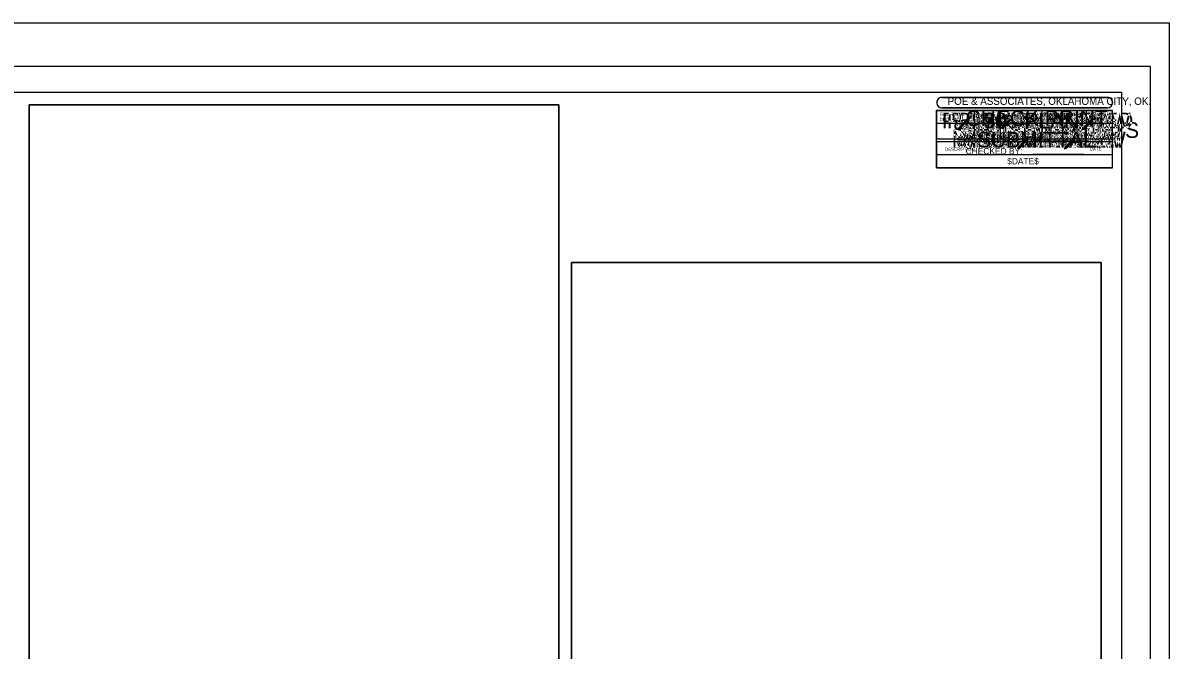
# Model space of a CAD drawing. Extents: x -1.6 to 34.4, y -1.2 to 22.8.
# Drawn here: x 12.44 to 34.36, y 10.82 to 22.82 of the extents above; entities that cross this region are included whole.
import ezdxf

# ---------------------------------------------------------------- set-up
doc = ezdxf.new("R2010")
doc.units = 0
for name, color, linetype in [('Default', 7, 'Continuous'), ('PR_OLE_MS_Excel', 7, 'Continuous'), ('SHT_Date_Stamp', 7, 'Continuous'), ('SHT_Plot_Shape_Full', 7, 'Continuous'), ('SHT_Plot_Shape_Half', 7, 'Continuous'), ('SHT_Sheet_Border', 7, 'Continuous'), ('SHT_Stamp_30_Submit', 7, 'Continuous'), ('SHT_Stamp_70_Submit', 7, 'Continuous'), ('SHT_Stamp_90_Submit', 7, 'Continuous'), ('SHT_Stamp_Check_Print', 7, 'Continuous'), ('SHT_Stamp_Est_Inf', 7, 'Continuous'), ('SHT_Stamp_FFR', 7, 'Continuous'), ('SHT_Stamp_Info_Material', 7, 'Continuous'), ('SHT_Stamp_No_Const', 7, 'Continuous'), ('SHT_Stamp_No_Design', 7, 'Continuous'), ('SHT_Stamp_Plan_Hand', 7, 'Continuous'), ('SHT_Stamp_Pre_Plan', 7, 'Continuous'), ('SHT_Stamp_Prop_RW', 7, 'Continuous'), ('SHT_Stamp_Ret_Sub', 7, 'Continuous'), ('SHT_Stamp_Rev_Block', 7, 'Continuous'), ('SHT_Stamp_Rev_Prop_RW', 7, 'Continuous'), ('SHT_Stamp_Rev_Sheet', 7, 'Continuous'), ('SHT_Stamp_RW_Utilities_Meeting', 7, 'Continuous'), ('SHT_Stamp_RW_Utilities_Review', 7, 'Continuous'), ('SHT_Stamp_Send_Comments', 7, 'Continuous')]:
    doc.layers.add(name, color=color, linetype=linetype)

msp = doc.modelspace()

# ---------------------------------------------------------------- linework, layer by layer
at = {"layer": 'Default'}
for points in [[(12.56, 2.371), (22.69, 2.371), (22.69, 21.26), (12.56, 21.26)], [(22.93, 2.371), (33.061, 2.371), (33.061, 18.239), (22.93, 18.239)]]:
    msp.add_lwpolyline(points, close=True, dxfattribs=at)
at = {"layer": 'PR_OLE_MS_Excel'}
for points in [[(12.56, 21.26), (22.69, 21.26), (22.69, 2.371), (12.56, 2.371)], [(22.93, 18.239), (33.061, 18.239), (33.061, 2.371), (22.93, 2.371)]]:
    msp.add_lwpolyline(points, close=True, dxfattribs=at)
at = {"layer": 'SHT_Plot_Shape_Full'}
msp.add_lwpolyline([(-1.638, 22.825), (34.362, 22.825), (34.362, -1.175), (-1.638, -1.175)], close=True, dxfattribs=at)
at = {"layer": 'SHT_Plot_Shape_Half'}
msp.add_lwpolyline([(0, 22), (34, 22), (34, 0), (0, 0)], close=True, dxfattribs=at)
at = {"layer": 'SHT_Sheet_Border'}
msp.add_lwpolyline([(33.45, 0.5), (1.95, 0.5), (1.95, 21.5), (33.45, 21.5)], close=True, dxfattribs=at)
at = {"layer": 'SHT_Stamp_30_Submit'}
for p, q in [((30.017, 21.4), (33.183, 21.4)), ((29.917, 21.15), (33.283, 21.15)), ((29.917, 20.051), (29.917, 21.15)), ((30.017, 21.2), (33.183, 21.2)), ((33.283, 20.051), (33.283, 21.15)), ((31.161, 20.812), (31.316, 20.984)), ((31.178, 20.812), (31.334, 20.984)), ((31.183, 20.812), (31.339, 20.984)), ((31.191, 20.812), (31.347, 20.984)), ((31.316, 20.984), (31.347, 20.984)), ((31.161, 20.812), (31.191, 20.812)), ((29.917, 20.051), (33.283, 20.051))]:
    msp.add_line(p, q, dxfattribs=at)
for centre, start, end in [((30.018, 21.3), 89.9952, 270), ((33.184, 21.3), 270, 90.0048)]:
    msp.add_arc(centre, 0.1, start, end, dxfattribs=at)
at = {"layer": 'SHT_Stamp_70_Submit'}
for p, q in [((30.017, 21.4), (33.183, 21.4)), ((29.917, 21.15), (33.283, 21.15)), ((29.917, 20.051), (29.917, 21.15)), ((30.017, 21.2), (33.183, 21.2)), ((33.283, 20.051), (33.283, 21.15)), ((31.161, 20.812), (31.316, 20.984)), ((31.178, 20.812), (31.334, 20.984)), ((31.183, 20.812), (31.339, 20.984)), ((31.191, 20.812), (31.347, 20.984)), ((31.316, 20.984), (31.347, 20.984)), ((31.161, 20.812), (31.191, 20.812)), ((29.917, 20.051), (33.283, 20.051))]:
    msp.add_line(p, q, dxfattribs=at)
for centre, start, end in [((30.018, 21.3), 89.9952, 270), ((33.184, 21.3), 270, 90.0048)]:
    msp.add_arc(centre, 0.1, start, end, dxfattribs=at)
at = {"layer": 'SHT_Stamp_90_Submit'}
for p, q in [((30.017, 21.4), (33.183, 21.4)), ((29.917, 21.15), (33.283, 21.15)), ((29.917, 20.051), (29.917, 21.15)), ((30.017, 21.2), (33.183, 21.2)), ((33.283, 20.051), (33.283, 21.15)), ((31.161, 20.812), (31.316, 20.984)), ((31.178, 20.812), (31.334, 20.984)), ((31.183, 20.812), (31.339, 20.984)), ((31.191, 20.812), (31.347, 20.984)), ((31.316, 20.984), (31.347, 20.984)), ((31.161, 20.812), (31.191, 20.812)), ((29.917, 20.051), (33.283, 20.051))]:
    msp.add_line(p, q, dxfattribs=at)
for centre, start, end in [((30.018, 21.3), 89.9952, 270), ((33.184, 21.3), 270, 90.0048)]:
    msp.add_arc(centre, 0.1, start, end, dxfattribs=at)
at = {"layer": 'SHT_Stamp_Check_Print'}
for p, q in [((30.017, 21.4), (33.183, 21.4)), ((29.917, 21.15), (33.283, 21.15)), ((29.917, 20.051), (29.917, 21.15)), ((30.017, 21.2), (33.183, 21.2)), ((33.283, 20.051), (33.283, 21.15)), ((31.759, 20.569), (32.73, 20.569)), ((31.759, 20.313), (32.73, 20.313)), ((29.917, 20.051), (33.283, 20.051))]:
    msp.add_line(p, q, dxfattribs=at)
for centre, start, end in [((30.018, 21.3), 89.9952, 270), ((33.184, 21.3), 270, 90.0048)]:
    msp.add_arc(centre, 0.1, start, end, dxfattribs=at)
at = {"layer": 'SHT_Stamp_Est_Inf'}
for p, q in [((30.017, 21.4), (33.183, 21.4)), ((29.917, 21.15), (33.283, 21.15)), ((29.917, 20.051), (29.917, 21.15)), ((30.017, 21.2), (33.183, 21.2)), ((33.283, 20.051), (33.283, 21.15)), ((29.917, 20.051), (33.283, 20.051))]:
    msp.add_line(p, q, dxfattribs=at)
for centre, start, end in [((30.018, 21.3), 89.9952, 270), ((33.184, 21.3), 270, 90.0048)]:
    msp.add_arc(centre, 0.1, start, end, dxfattribs=at)
at = {"layer": 'SHT_Stamp_FFR'}
for p, q in [((30.017, 21.4), (33.183, 21.4)), ((29.917, 21.15), (33.283, 21.15)), ((29.917, 20.051), (29.917, 21.15)), ((30.017, 21.2), (33.183, 21.2)), ((33.283, 20.051), (33.283, 21.15)), ((29.917, 20.051), (33.283, 20.051))]:
    msp.add_line(p, q, dxfattribs=at)
for centre, start, end in [((30.018, 21.3), 89.9952, 270), ((33.184, 21.3), 270, 90.0048)]:
    msp.add_arc(centre, 0.1, start, end, dxfattribs=at)
at = {"layer": 'SHT_Stamp_Info_Material'}
for p, q in [((30.017, 21.4), (33.183, 21.4)), ((29.917, 21.15), (33.283, 21.15)), ((29.917, 20.051), (29.917, 21.15)), ((30.017, 21.2), (33.183, 21.2)), ((33.283, 20.051), (33.283, 21.15)), ((29.917, 20.051), (33.283, 20.051))]:
    msp.add_line(p, q, dxfattribs=at)
for centre, start, end in [((30.018, 21.3), 89.9952, 270), ((33.184, 21.3), 270, 90.0048)]:
    msp.add_arc(centre, 0.1, start, end, dxfattribs=at)
at = {"layer": 'SHT_Stamp_No_Const'}
for p, q in [((30.017, 21.4), (33.183, 21.4)), ((29.917, 21.15), (33.283, 21.15)), ((29.917, 20.051), (29.917, 21.15)), ((30.017, 21.2), (33.183, 21.2)), ((33.283, 20.051), (33.283, 21.15)), ((29.917, 20.051), (33.283, 20.051))]:
    msp.add_line(p, q, dxfattribs=at)
for centre, start, end in [((30.018, 21.3), 89.9952, 270), ((33.184, 21.3), 270, 90.0048)]:
    msp.add_arc(centre, 0.1, start, end, dxfattribs=at)
at = {"layer": 'SHT_Stamp_No_Design'}
for p, q in [((30.017, 21.4), (33.183, 21.4)), ((29.917, 21.15), (33.283, 21.15)), ((29.917, 20.051), (29.917, 21.15)), ((30.017, 21.2), (33.183, 21.2)), ((33.283, 20.051), (33.283, 21.15)), ((29.917, 20.051), (33.283, 20.051))]:
    msp.add_line(p, q, dxfattribs=at)
for centre, start, end in [((30.018, 21.3), 89.9952, 270), ((33.184, 21.3), 270, 90.0048)]:
    msp.add_arc(centre, 0.1, start, end, dxfattribs=at)
at = {"layer": 'SHT_Stamp_Plan_Hand'}
for p, q in [((30.017, 21.4), (33.183, 21.4)), ((29.917, 21.15), (33.283, 21.15)), ((29.917, 20.051), (29.917, 21.15)), ((30.017, 21.2), (33.183, 21.2)), ((33.283, 20.051), (33.283, 21.15)), ((29.917, 20.051), (33.283, 20.051))]:
    msp.add_line(p, q, dxfattribs=at)
for centre, start, end in [((30.018, 21.3), 89.9952, 270), ((33.184, 21.3), 270, 90.0048)]:
    msp.add_arc(centre, 0.1, start, end, dxfattribs=at)
at = {"layer": 'SHT_Stamp_Pre_Plan'}
for p, q in [((30.017, 21.4), (33.183, 21.4)), ((29.917, 21.15), (33.283, 21.15)), ((29.917, 20.051), (29.917, 21.15)), ((30.017, 21.2), (33.183, 21.2)), ((33.283, 20.051), (33.283, 21.15)), ((29.917, 20.051), (33.283, 20.051))]:
    msp.add_line(p, q, dxfattribs=at)
for centre, start, end in [((30.018, 21.3), 89.9952, 270), ((33.184, 21.3), 270, 90.0048)]:
    msp.add_arc(centre, 0.1, start, end, dxfattribs=at)
at = {"layer": 'SHT_Stamp_Prop_RW'}
for p, q in [((30.017, 21.4), (33.183, 21.4)), ((30.017, 21.4), (33.183, 21.4)), ((29.917, 21.15), (33.283, 21.15)), ((29.917, 20.051), (29.917, 21.15)), ((29.917, 21.15), (33.283, 21.15)), ((29.917, 20.051), (29.917, 21.15)), ((30.017, 21.2), (33.183, 21.2)), ((30.017, 21.2), (33.183, 21.2)), ((33.283, 20.051), (33.283, 21.15)), ((33.283, 20.051), (33.283, 21.15)), ((31.464, 20.423), (31.656, 20.636)), ((31.464, 20.423), (31.656, 20.636)), ((31.486, 20.423), (31.678, 20.636)), ((31.486, 20.423), (31.678, 20.636)), ((31.492, 20.423), (31.684, 20.636)), ((31.492, 20.423), (31.684, 20.636)), ((31.502, 20.423), (31.694, 20.636)), ((31.502, 20.423), (31.694, 20.636)), ((31.656, 20.636), (31.694, 20.636)), ((31.656, 20.636), (31.694, 20.636)), ((31.464, 20.423), (31.502, 20.423)), ((31.464, 20.423), (31.502, 20.423)), ((29.917, 20.051), (33.283, 20.051)), ((29.917, 20.051), (33.283, 20.051))]:
    msp.add_line(p, q, dxfattribs=at)
for centre, start, end in [((30.018, 21.3), 89.9952, 270), ((30.018, 21.3), 89.9952, 270), ((33.184, 21.3), 270, 90.0048), ((33.184, 21.3), 270, 90.0048)]:
    msp.add_arc(centre, 0.1, start, end, dxfattribs=at)
at = {"layer": 'SHT_Stamp_Ret_Sub'}
for p, q in [((30.017, 21.4), (33.183, 21.4)), ((29.917, 21.15), (33.283, 21.15)), ((29.917, 20.051), (29.917, 21.15)), ((30.017, 21.2), (33.183, 21.2)), ((33.283, 20.051), (33.283, 21.15)), ((29.917, 20.051), (33.283, 20.051))]:
    msp.add_line(p, q, dxfattribs=at)
for centre, start, end in [((30.018, 21.3), 89.9952, 270), ((33.184, 21.3), 270, 90.0048)]:
    msp.add_arc(centre, 0.1, start, end, dxfattribs=at)
at = {"layer": 'SHT_Stamp_Rev_Block'}
for p, q in [((33.183, 21.4), (30.018, 21.4)), ((33.283, 21.15), (29.917, 21.15)), ((29.917, 21.15), (29.917, 20.6)), ((33.183, 21.2), (30.018, 21.2)), ((30.633, 21.15), (30.633, 20.6)), ((31.133, 21.15), (31.133, 20.6)), ((31.933, 20.6), (31.933, 21.15)), ((32.333, 20.6), (32.333, 21.15)), ((32.783, 20.6), (32.783, 21.15)), ((33.283, 20.6), (33.283, 21.15)), ((33.283, 20.9), (29.917, 20.9)), ((33.283, 20.6), (29.917, 20.6)), ((33.283, 20.55), (29.917, 20.55)), ((29.917, 20.55), (29.917, 20.05)), ((33.283, 20.05), (33.283, 20.55)), ((33.283, 20.3), (29.917, 20.3)), ((33.283, 20.05), (29.917, 20.05))]:
    msp.add_line(p, q, dxfattribs=at)
for centre, start, end in [((30.018, 21.299), 90, 270), ((33.183, 21.3), 270, 90)]:
    msp.add_arc(centre, 0.1, start, end, dxfattribs=at)
at = {"layer": 'SHT_Stamp_Rev_Prop_RW'}
for p, q in [((30.017, 21.4), (33.183, 21.4)), ((29.917, 21.15), (33.283, 21.15)), ((29.917, 20.051), (29.917, 21.15)), ((30.017, 21.2), (33.183, 21.2)), ((33.283, 20.051), (33.283, 21.15)), ((32.354, 20.42), (32.546, 20.633)), ((32.376, 20.42), (32.568, 20.633)), ((32.383, 20.42), (32.575, 20.633)), ((32.392, 20.42), (32.584, 20.633)), ((32.546, 20.633), (32.584, 20.633)), ((32.354, 20.42), (32.392, 20.42)), ((29.917, 20.051), (33.283, 20.051))]:
    msp.add_line(p, q, dxfattribs=at)
for centre, start, end in [((30.018, 21.3), 89.9952, 270), ((33.184, 21.3), 270, 90.0048)]:
    msp.add_arc(centre, 0.1, start, end, dxfattribs=at)
at = {"layer": 'SHT_Stamp_Rev_Sheet'}
for p, q in [((30.017, 21.4), (33.183, 21.4)), ((29.917, 21.15), (33.283, 21.15)), ((29.917, 20.051), (29.917, 21.15)), ((30.017, 21.2), (33.183, 21.2)), ((33.283, 20.051), (33.283, 21.15)), ((29.917, 20.051), (33.283, 20.051))]:
    msp.add_line(p, q, dxfattribs=at)
for centre, start, end in [((30.018, 21.3), 89.9952, 270), ((33.184, 21.3), 270, 90.0048)]:
    msp.add_arc(centre, 0.1, start, end, dxfattribs=at)
at = {"layer": 'SHT_Stamp_RW_Utilities_Meeting'}
for p, q in [((30.017, 21.4), (33.183, 21.4)), ((29.917, 21.15), (33.283, 21.15)), ((29.917, 20.051), (29.917, 21.15)), ((30.017, 21.2), (33.183, 21.2)), ((33.283, 20.051), (33.283, 21.15)), ((30.319, 20.789), (30.511, 21.003)), ((30.341, 20.789), (30.533, 21.003)), ((30.348, 20.789), (30.54, 21.003)), ((30.357, 20.789), (30.549, 21.003)), ((30.511, 21.003), (30.549, 21.003)), ((30.319, 20.789), (30.357, 20.789)), ((29.917, 20.051), (33.283, 20.051))]:
    msp.add_line(p, q, dxfattribs=at)
for centre, start, end in [((30.018, 21.3), 89.9952, 270), ((33.184, 21.3), 270, 90.0048)]:
    msp.add_arc(centre, 0.1, start, end, dxfattribs=at)
at = {"layer": 'SHT_Stamp_RW_Utilities_Review'}
for p, q in [((30.017, 21.4), (33.183, 21.4)), ((29.917, 21.15), (33.283, 21.15)), ((29.917, 20.051), (29.917, 21.15)), ((30.017, 21.2), (33.183, 21.2)), ((33.283, 20.051), (33.283, 21.15)), ((32.708, 20.789), (32.9, 21.003)), ((32.73, 20.789), (32.922, 21.003)), ((32.736, 20.789), (32.928, 21.003)), ((32.746, 20.789), (32.938, 21.003)), ((32.9, 21.003), (32.938, 21.003)), ((32.708, 20.789), (32.746, 20.789)), ((29.917, 20.051), (33.283, 20.051))]:
    msp.add_line(p, q, dxfattribs=at)
for centre, start, end in [((30.018, 21.3), 89.9952, 270), ((33.184, 21.3), 270, 90.0048)]:
    msp.add_arc(centre, 0.1, start, end, dxfattribs=at)
at = {"layer": 'SHT_Stamp_Send_Comments'}
for p, q in [((30.017, 21.4), (33.183, 21.4)), ((29.917, 21.15), (33.283, 21.15)), ((29.917, 20.051), (29.917, 21.15)), ((30.017, 21.2), (33.183, 21.2)), ((33.283, 20.051), (33.283, 21.15)), ((29.917, 20.051), (33.283, 20.051))]:
    msp.add_line(p, q, dxfattribs=at)
for centre, start, end in [((30.018, 21.3), 89.9952, 270), ((33.184, 21.3), 270, 90.0048)]:
    msp.add_arc(centre, 0.1, start, end, dxfattribs=at)

# ---------------------------------------------------------------- texts
at = {"layer": 'SHT_Date_Stamp'}
msp.add_text('$DATE$', height=0.12, dxfattribs=at).set_placement((31.266, 20.119))
at = {"layer": 'SHT_Stamp_30_Submit'}
for s, height, p in [('POE & ASSOCIATES, OKLAHOMA CITY, OK.', 0.14, (30.127, 21.257)), ('30   PLAN', 0.3, (30.82, 20.808)), ('O', 0.153, (31.126, 20.897)), ('O', 0.153, (31.278, 20.812)), ('SUBMITTAL', 0.3, (30.689, 20.441))]:
    msp.add_text(s, height=height, dxfattribs=at).set_placement(p)
at = {"layer": 'SHT_Stamp_70_Submit'}
for s, height, p in [('POE & ASSOCIATES, OKLAHOMA CITY, OK.', 0.14, (30.127, 21.257)), ('70   PLAN', 0.3, (30.813, 20.808)), ('O', 0.153, (31.126, 20.897)), ('O', 0.153, (31.278, 20.812)), ('SUBMITTAL', 0.3, (30.689, 20.441))]:
    msp.add_text(s, height=height, dxfattribs=at).set_placement(p)
at = {"layer": 'SHT_Stamp_90_Submit'}
for s, height, p in [('POE & ASSOCIATES, OKLAHOMA CITY, OK.', 0.14, (30.127, 21.257)), ('90   PLAN', 0.3, (30.813, 20.808)), ('O', 0.153, (31.126, 20.897)), ('O', 0.153, (31.278, 20.812)), ('SUBMITTAL', 0.3, (30.689, 20.441))]:
    msp.add_text(s, height=height, dxfattribs=at).set_placement(p)
at = {"layer": 'SHT_Stamp_Check_Print'}
for s, height, p in [('POE & ASSOCIATES, OKLAHOMA CITY, OK.', 0.14, (30.128, 21.258)), ('CHECK PRINT', 0.3, (30.47, 20.851)), ('REVISED BY:', 0.12, (30.471, 20.568)), ('CHECKED BY:', 0.12, (30.471, 20.313))]:
    msp.add_text(s, height=height, dxfattribs=at).set_placement(p)
at = {"layer": 'SHT_Stamp_Est_Inf'}
for s, height, p in [('POE & ASSOCIATES, OKLAHOMA CITY, OK.', 0.14, (30.128, 21.258)), ('BASED ON EST.', 0.3, (30.348, 20.808)), ('INFORMATION', 0.3, (30.47, 20.441))]:
    msp.add_text(s, height=height, dxfattribs=at).set_placement(p)
at = {"layer": 'SHT_Stamp_FFR'}
for s, height, p in [('POE & ASSOCIATES, OKLAHOMA CITY, OK.', 0.14, (30.128, 21.258)), ('FINAL FIELD', 0.3, (30.569, 20.808)), ('REVIEW', 0.3, (30.997, 20.441))]:
    msp.add_text(s, height=height, dxfattribs=at).set_placement(p)
at = {"layer": 'SHT_Stamp_Info_Material'}
for s, height, p in [('POE & ASSOCIATES, OKLAHOMA CITY, OK.', 0.14, (30.128, 21.258)), ('INFORMATION', 0.3, (30.47, 20.808)), ('MATERIAL ONLY', 0.3, (30.211, 20.441))]:
    msp.add_text(s, height=height, dxfattribs=at).set_placement(p)
at = {"layer": 'SHT_Stamp_No_Const'}
for s, height, p in [('POE & ASSOCIATES, OKLAHOMA CITY, OK.', 0.14, (30.128, 21.258)), ('NOT TO BE USED', 0.3, (30.158, 20.808)), ('FOR CONST.', 0.3, (30.648, 20.441))]:
    msp.add_text(s, height=height, dxfattribs=at).set_placement(p)
at = {"layer": 'SHT_Stamp_No_Design'}
for s, height, p in [('POE & ASSOCIATES, OKLAHOMA CITY, OK.', 0.14, (30.128, 21.258)), ('NOT TO BE USED', 0.3, (30.158, 20.808)), ('FOR DESIGN', 0.3, (30.631, 20.441))]:
    msp.add_text(s, height=height, dxfattribs=at).set_placement(p)
at = {"layer": 'SHT_Stamp_Plan_Hand'}
for s, height, p in [('POE & ASSOCIATES, OKLAHOMA CITY, OK.', 0.14, (30.128, 21.258)), ('PLAN-IN-HAND', 0.3, (30.402, 20.625))]:
    msp.add_text(s, height=height, dxfattribs=at).set_placement(p)
at = {"layer": 'SHT_Stamp_Pre_Plan'}
for s, height, p in [('POE & ASSOCIATES, OKLAHOMA CITY, OK.', 0.14, (30.128, 21.258)), ('PRELIMINARY', 0.3, (30.485, 20.808)), ('PLANS', 0.3, (31.093, 20.441))]:
    msp.add_text(s, height=height, dxfattribs=at).set_placement(p)
at = {"layer": 'SHT_Stamp_Prop_RW'}
for s, height, p in [('POE & ASSOCIATES, OKLAHOMA CITY, OK.', 0.14, (30.128, 21.258)), ('POE & ASSOCIATES, OKLAHOMA CITY, OK.', 0.14, (30.128, 21.258)), ('PROPOSED', 0.3, (30.827, 20.808)), ('PROPOSED', 0.3, (30.827, 20.808)), ('R W', 0.3, (31.259, 20.441)), ('R W', 0.3, (31.259, 20.441))]:
    msp.add_text(s, height=height, dxfattribs=at).set_placement(p)
at = {"layer": 'SHT_Stamp_Ret_Sub'}
for s, height, p in [('POE & ASSOCIATES, OKLAHOMA CITY, OK.', 0.14, (30.128, 21.258)), ('RET. SUBMITTED', 0.3, (30.335, 20.808)), ('MATERIALS', 0.3, (30.677, 20.441))]:
    msp.add_text(s, height=height, dxfattribs=at).set_placement(p)
at = {"layer": 'SHT_Stamp_Rev_Block'}
for s, height, p in [('POE & ASSOCIATES, OKLAHOMA CITY, OK.', 0.14, (30.128, 21.258)), ('FED.  ROAD', 0.06, (29.973, 21.045)), ('STATE', 0.06, (30.746, 20.995)), ('JOB PIECE NO.', 0.06, (31.165, 20.995)), ('FISCAL', 0.06, (31.966, 21.045)), ('SHEET', 0.06, (32.421, 21.045)), ('TOTAL', 0.06, (32.896, 21.045)), ('DIST.  NO.', 0.06, (29.973, 20.949)), ('YEAR', 0.06, (32.025, 20.949)), ('NO.', 0.06, (32.48, 20.945)), ('SHEETS', 0.06, (32.865, 20.949)), ('6', 0.08, (30.233, 20.71)), ('OKLA.', 0.08, (30.7, 20.71)), ('DESCRIPTION', 0.06, (30.077, 20.378)), ('REVISIONS', 0.06, (31.326, 20.437)), ('DATE', 0.06, (32.847, 20.382))]:
    msp.add_text(s, height=height, dxfattribs=at).set_placement(p)
at = {"layer": 'SHT_Stamp_Rev_Prop_RW'}
for s, height, p in [('POE & ASSOCIATES, OKLAHOMA CITY, OK.', 0.14, (30.128, 21.258)), ('REVISED', 0.3, (30.954, 20.808)), ('PROPOSED R W', 0.3, (30.369, 20.441))]:
    msp.add_text(s, height=height, dxfattribs=at).set_placement(p)
at = {"layer": 'SHT_Stamp_Rev_Sheet'}
for s, height, p in [('POE & ASSOCIATES, OKLAHOMA CITY, OK.', 0.14, (30.128, 21.258)), ('REVISED SHEET', 0.3, (30.352, 20.625))]:
    msp.add_text(s, height=height, dxfattribs=at).set_placement(p)
at = {"layer": 'SHT_Stamp_RW_Utilities_Meeting'}
for s, height, p in [('POE & ASSOCIATES, OKLAHOMA CITY, OK.', 0.14, (30.127, 21.257)), ('R W & UTILITIES', 0.3, (30.112, 20.808)), ('MEETING', 0.3, (30.881, 20.441))]:
    msp.add_text(s, height=height, dxfattribs=at).set_placement(p)
at = {"layer": 'SHT_Stamp_RW_Utilities_Review'}
for s, height, p in [('POE & ASSOCIATES, OKLAHOMA CITY, OK.', 0.14, (30.127, 21.257)), ('PRELIMINARY R W', 0.3, (30.017, 20.808)), ('& UTIL.  REVIEW', 0.3, (30.3, 20.441))]:
    msp.add_text(s, height=height, dxfattribs=at).set_placement(p)
at = {"layer": 'SHT_Stamp_Send_Comments'}
for s, height, p in [('POE & ASSOCIATES, OKLAHOMA CITY, OK.', 0.14, (30.128, 21.258)), ('SEND COMMENTS', 0.3, (30.223, 20.625))]:
    msp.add_text(s, height=height, dxfattribs=at).set_placement(p)

doc.saveas('drawing.dxf')
